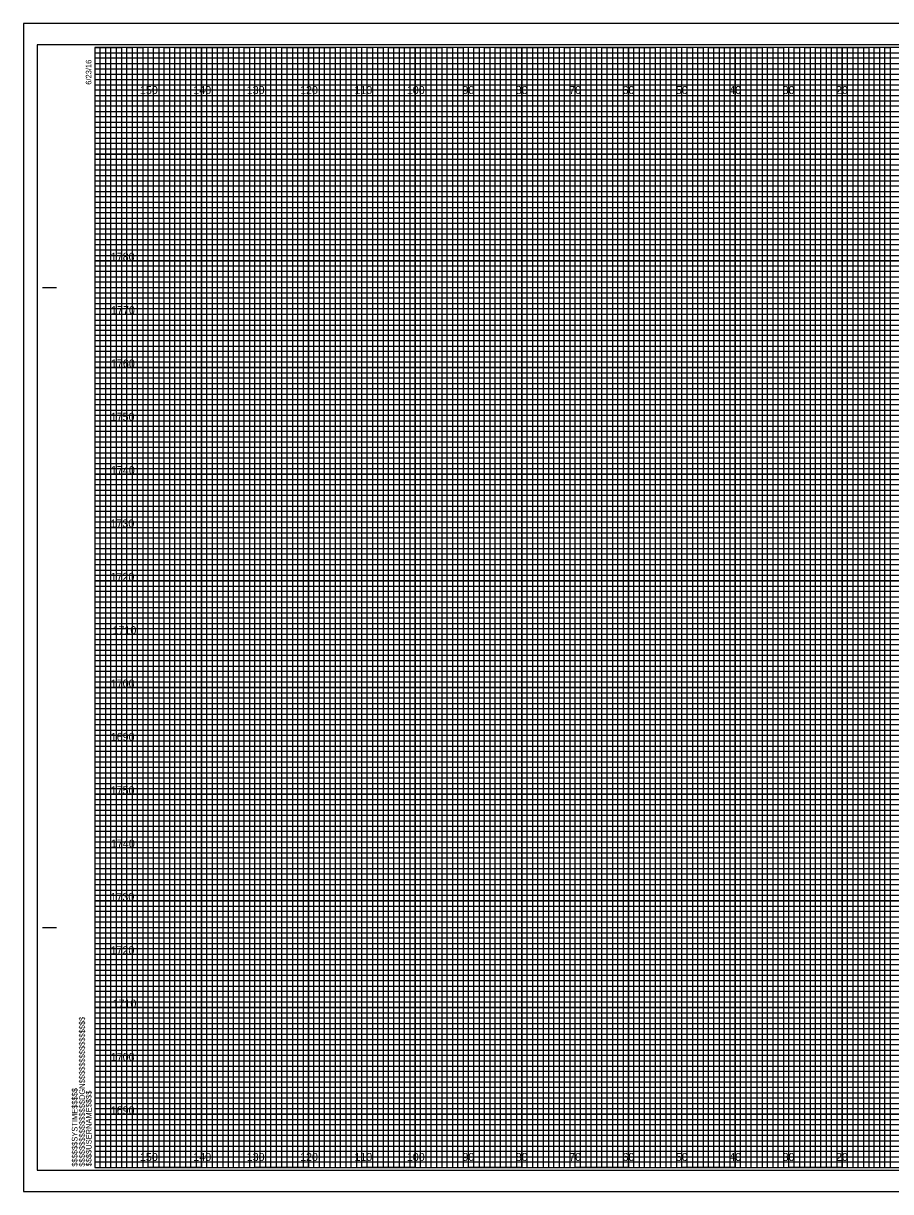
# Model space of a CAD drawing. Extents: x 185 to 522, y -7 to 872.
# Drawn here: x 184.8 to 347.3, y 433.5 to 652.5 of the extents above; entities that cross this region are included whole.
import ezdxf

# ---------------------------------------------------------------- set-up
doc = ezdxf.new("R2010")
doc.units = 0
for name, color, linetype in [('Raster_Level_0', 7, 'Continuous'), ('Scratch_Level_3', 7, 'Continuous'), ('Sheet Cross Section CELL', 7, 'Continuous'), ('Sheet Cross Section Grid Major CELL', 7, 'Continuous'), ('Sheet Cross Section Grid Middle CELL', 7, 'Continuous'), ('Sheet Cross Section Grid Minor 1 CELL', 7, 'Continuous'), ('Sheet Cross Section Grid Minor 2 CELL', 7, 'Continuous'), ('Sheet Cutting Line CELL', 7, 'Continuous'), ('Sheet DOT Grid CELL', 7, 'Continuous'), ('Sheet Plot Border Inside CELL', 7, 'Continuous'), ('Sheet Plot Border Outside CELL', 7, 'Continuous')]:
    doc.layers.add(name, color=color, linetype=linetype)

msp = doc.modelspace()

# ---------------------------------------------------------------- linework, layer by layer
at = {"layer": 'Sheet Cross Section CELL'}
for p, q in [((188.44, 602.95), (190.94, 602.95)), ((188.54, 602.95), (191.04, 602.95)), ((188.44, 482.95), (190.94, 482.95)), ((188.54, 482.95), (191.04, 482.95)), ((198.24, 437.95), (198.24, 437.95)), ((198.24, 437.95), (198.24, 437.95)), ((198.24, 437.95), (198.24, 437.95)), ((198.24, 437.95), (198.24, 437.95)), ((198.24, 437.95), (198.24, 437.95)), ((198.24, 437.95), (198.24, 437.95)), ((198.24, 437.95), (198.24, 437.95))]:
    msp.add_line(p, q, dxfattribs=at)
msp.add_lwpolyline([(518.24, 647.95), (198.24, 647.95), (198.24, 437.95), (518.24, 437.95)], close=True, dxfattribs=at)
at = {"layer": 'Sheet Cross Section Grid Major CELL'}
for p, q in [((208.24, 647.95), (198.24, 647.95)), ((208.24, 437.95), (208.24, 647.95)), ((228.24, 647.95), (218.24, 647.95)), ((218.24, 647.95), (218.24, 437.95)), ((228.24, 437.95), (228.24, 647.95)), ((248.24, 647.95), (238.24, 647.95)), ((238.24, 647.95), (238.24, 437.95)), ((248.24, 437.95), (248.24, 647.95)), ((268.24, 647.95), (258.24, 647.95)), ((258.24, 647.95), (258.24, 437.95)), ((268.24, 437.95), (268.24, 647.95)), ((288.24, 647.95), (278.24, 647.95)), ((278.24, 647.95), (278.24, 437.95)), ((288.24, 437.95), (288.24, 647.95)), ((308.24, 647.95), (298.24, 647.95)), ((298.24, 647.95), (298.24, 437.95)), ((308.24, 437.95), (308.24, 647.95)), ((328.24, 647.95), (318.24, 647.95)), ((318.24, 647.95), (318.24, 437.95)), ((328.24, 437.95), (328.24, 647.95)), ((348.24, 647.95), (338.24, 647.95)), ((338.24, 647.95), (338.24, 437.95)), ((218.24, 437.95), (208.24, 437.95)), ((238.24, 437.95), (228.24, 437.95)), ((258.24, 437.95), (248.24, 437.95)), ((278.24, 437.95), (268.24, 437.95)), ((298.24, 437.95), (288.24, 437.95)), ((318.24, 437.95), (308.24, 437.95)), ((338.24, 437.95), (328.24, 437.95))]:
    msp.add_line(p, q, dxfattribs=at)
for points in [[(198.24, 637.95), (518.24, 637.95), (518.24, 627.95), (198.24, 627.95)], [(198.24, 617.95), (518.24, 617.95), (518.24, 607.95), (198.24, 607.95)], [(198.24, 597.95), (518.24, 597.95), (518.24, 587.95), (198.24, 587.95)], [(198.24, 577.95), (518.24, 577.95), (518.24, 567.95), (198.24, 567.95)], [(198.24, 557.95), (518.24, 557.95), (518.24, 547.95), (198.24, 547.95)], [(198.24, 537.95), (518.24, 537.95), (518.24, 527.95), (198.24, 527.95)], [(198.24, 517.95), (518.24, 517.95), (518.24, 507.95), (198.24, 507.95)], [(198.24, 497.95), (518.24, 497.95), (518.24, 487.95), (198.24, 487.95)], [(198.24, 477.95), (518.24, 477.95), (518.24, 467.95), (198.24, 467.95)], [(198.24, 457.95), (518.24, 457.95), (518.24, 447.95), (198.24, 447.95)]]:
    msp.add_lwpolyline(points, dxfattribs=at)
at = {"layer": 'Sheet Cross Section Grid Middle CELL'}
for points in [[(198.24, 647.95), (203.24, 647.95), (203.24, 437.95), (213.24, 437.95), (213.24, 647.95), (223.24, 647.95), (223.24, 437.95), (233.24, 437.95), (233.24, 647.95), (243.24, 647.95), (243.24, 437.95), (253.24, 437.95), (253.24, 647.95), (263.24, 647.95), (263.24, 437.95), (273.24, 437.95), (273.24, 647.95), (283.24, 647.95), (283.24, 437.95), (293.24, 437.95), (293.24, 647.95), (303.24, 647.95), (303.24, 437.95), (313.24, 437.95), (313.24, 647.95), (323.24, 647.95), (323.24, 437.95), (333.24, 437.95), (333.24, 647.95), (343.24, 647.95), (343.24, 437.95), (353.24, 437.95)], [(198.24, 642.95), (473.24, 642.95)], [(198.24, 622.95), (518.24, 622.95), (518.24, 632.95), (198.24, 632.95)], [(198.24, 602.95), (518.24, 602.95), (518.24, 612.95), (198.24, 612.95)], [(198.24, 582.95), (518.24, 582.95), (518.24, 592.95), (198.24, 592.95)], [(198.24, 562.95), (518.24, 562.95), (518.24, 572.95), (198.24, 572.95)], [(198.24, 542.95), (518.24, 542.95), (518.24, 552.95), (198.24, 552.95)], [(198.24, 522.95), (518.24, 522.95), (518.24, 532.95), (198.24, 532.95)], [(198.24, 502.95), (518.24, 502.95), (518.24, 512.95), (198.24, 512.95)], [(198.24, 482.95), (518.24, 482.95), (518.24, 492.95), (198.24, 492.95)], [(198.24, 462.95), (518.24, 462.95), (518.24, 472.95), (198.24, 472.95)], [(198.24, 442.95), (518.24, 442.95), (518.24, 452.95), (198.24, 452.95)]]:
    msp.add_lwpolyline(points, dxfattribs=at)
at = {"layer": 'Sheet Cross Section Grid Minor 1 CELL'}
for p, q in [((198.24, 646.95), (458.24, 646.95)), ((458.24, 645.93), (198.24, 645.93)), ((198.24, 645.93), (198.24, 644.95)), ((198.24, 644.95), (458.24, 644.95)), ((458.24, 643.84), (198.24, 643.84)), ((198.24, 643.84), (198.24, 641.95)), ((198.24, 641.95), (518.24, 641.95))]:
    msp.add_line(p, q, dxfattribs=at)
for points in [[(198.24, 640.95), (468.24, 640.95), (518.24, 640.95), (518.24, 639.95), (198.24, 639.95)], [(198.24, 638.95), (518.24, 638.95), (518.24, 636.95), (198.24, 636.95)], [(198.24, 635.95), (518.24, 635.95), (518.24, 634.95), (198.24, 634.93)], [(198.24, 633.95), (518.24, 633.95), (518.24, 631.95), (198.24, 631.95)], [(198.24, 630.95), (518.24, 630.95), (518.24, 629.95), (198.24, 629.95)], [(198.24, 628.95), (518.24, 628.95), (518.24, 626.95), (198.24, 626.95)], [(198.24, 625.95), (518.24, 625.95), (518.24, 624.95), (198.24, 624.95)], [(198.24, 623.95), (518.24, 623.95), (518.24, 621.95), (198.24, 621.95)], [(198.24, 620.95), (518.24, 620.95), (518.24, 619.95), (198.24, 619.95)], [(198.24, 618.95), (518.24, 618.95), (518.24, 616.95), (198.24, 616.95)], [(198.24, 615.95), (518.24, 615.95), (518.24, 614.95), (198.24, 614.95)], [(198.24, 613.95), (518.24, 613.95), (518.24, 611.9), (518.24, 610.95), (518.24, 609.95), (198.24, 609.95)], [(198.24, 611.95), (518.24, 611.95), (518.24, 610.95), (198.24, 610.95)], [(198.24, 608.95), (518.24, 608.95), (518.24, 606.95), (198.24, 606.98)], [(198.24, 606.98), (518.24, 606.95), (518.24, 605.95), (198.24, 605.95)], [(198.24, 604.95), (518.24, 604.95), (518.24, 603.95), (198.24, 603.95)], [(198.24, 601.95), (518.24, 601.95), (518.24, 600.95), (198.24, 600.95)], [(198.24, 599.95), (518.24, 599.95), (518.24, 598.95), (198.24, 598.95)], [(198.17, 596.84), (518.24, 596.84), (518.24, 595.83), (198.17, 595.83)], [(198.24, 594.95), (518.24, 594.95), (518.24, 593.95), (198.24, 593.95)], [(198.24, 591.95), (518.24, 591.95), (518.24, 590.95), (198.24, 590.95)], [(198.24, 589.95), (518.24, 589.95), (518.24, 588.95), (198.24, 588.95)], [(198.24, 586.95), (518.24, 586.95), (518.24, 585.95), (198.24, 585.95)], [(198.24, 584.95), (518.24, 584.95), (518.24, 583.95), (198.24, 583.95)], [(198.24, 581.95), (518.24, 581.95), (518.24, 580.95), (198.24, 580.95)], [(198.24, 579.95), (518.24, 579.95), (518.24, 578.95), (198.24, 578.95)], [(198.24, 576.95), (518.24, 576.95), (518.23, 575.93), (198.24, 575.95)], [(198.24, 574.95), (518.24, 574.95), (518.24, 573.95), (198.24, 573.95)], [(198.24, 571.95), (518.24, 571.95), (518.24, 570.95), (198.24, 570.95)], [(198.24, 569.95), (518.24, 569.95), (518.24, 568.95), (198.24, 568.95)], [(198.24, 566.95), (518.24, 566.95), (518.24, 565.95), (198.24, 565.95)], [(198.24, 564.95), (518.24, 564.95), (518.24, 563.95), (198.24, 563.95)], [(198.24, 561.95), (518.24, 561.95), (518.24, 560.95), (198.24, 560.95)], [(198.24, 559.95), (518.24, 559.95), (518.24, 558.95), (198.24, 558.95)], [(198.24, 556.95), (518.24, 556.95), (518.24, 555.95), (198.24, 555.95)], [(198.24, 554.94), (518.31, 554.86), (518.24, 553.95), (198.24, 553.95)], [(198.24, 551.95), (518.24, 551.95), (518.24, 550.95), (198.24, 550.95)], [(198.24, 549.95), (518.24, 549.95), (518.24, 548.95), (198.24, 548.95)], [(198.24, 546.95), (518.24, 546.95), (518.24, 545.95), (198.24, 545.95)], [(198.24, 544.95), (518.24, 544.95), (518.24, 543.95), (198.24, 543.95)], [(198.24, 541.95), (518.24, 541.95), (518.24, 540.95), (198.24, 540.95)], [(198.24, 539.95), (518.24, 539.95), (518.24, 538.95), (198.24, 538.95)], [(198.24, 536.95), (518.24, 536.95), (518.24, 535.95), (198.24, 535.95)], [(198.24, 534.95), (518.24, 534.95), (518.24, 533.95), (198.24, 533.95)], [(198.24, 531.95), (518.24, 531.95), (518.24, 530.95), (198.24, 530.95)], [(198.24, 529.95), (518.24, 529.95), (518.24, 528.95), (198.24, 528.95)], [(198.24, 526.95), (518.24, 526.95), (518.24, 525.95), (198.24, 525.95)], [(198.24, 524.95), (518.24, 524.95), (518.24, 523.95), (198.24, 523.95)], [(198.24, 521.95), (518.24, 521.95), (518.24, 520.95), (198.24, 520.95)], [(198.24, 519.95), (518.24, 519.95), (518.24, 518.95), (198.24, 518.95)], [(198.24, 516.95), (518.24, 516.95), (518.23, 515.93), (198.24, 515.95)], [(198.24, 514.95), (518.24, 514.95), (518.24, 513.95), (198.24, 513.95)], [(198.24, 511.95), (518.24, 511.95), (518.24, 510.95), (198.24, 510.95)], [(198.24, 509.95), (518.24, 509.95), (518.24, 508.95), (198.24, 508.95)], [(198.24, 506.95), (518.24, 506.95), (518.24, 505.95), (198.24, 505.95)], [(198.24, 504.95), (518.24, 504.95), (518.24, 503.95), (198.24, 503.95)], [(198.24, 501.95), (518.24, 501.95), (518.24, 500.95), (198.24, 500.95)], [(198.24, 499.95), (518.24, 499.95), (518.24, 498.95), (198.24, 498.95)], [(198.24, 496.95), (518.24, 496.95), (518.24, 495.95), (198.24, 495.95)], [(198.24, 494.94), (518.31, 494.86), (518.24, 493.95), (198.24, 493.95)], [(198.24, 491.95), (518.24, 491.95), (518.24, 490.95), (198.24, 490.95)], [(198.24, 489.95), (518.24, 489.95), (518.24, 488.95), (198.24, 488.95)], [(198.24, 486.95), (518.24, 486.95), (518.24, 485.95), (198.24, 485.95)], [(198.24, 484.95), (518.24, 484.95), (518.24, 483.95), (198.24, 483.95)], [(198.24, 481.95), (518.24, 481.95), (518.24, 480.95), (198.24, 480.95)], [(198.24, 479.95), (518.24, 479.95), (518.24, 478.95), (198.24, 478.95)], [(198.24, 476.95), (518.24, 476.95), (518.24, 475.95), (198.24, 475.95)], [(198.24, 474.95), (518.24, 474.95), (518.24, 473.95), (198.24, 473.95)], [(198.24, 471.95), (518.24, 471.95), (518.24, 470.95), (198.24, 470.95)], [(198.24, 469.95), (518.24, 469.95), (518.24, 468.95), (198.24, 468.95)], [(198.24, 466.95), (518.24, 466.95), (518.24, 465.95), (198.24, 465.95)], [(198.24, 464.95), (518.24, 464.95), (518.24, 463.95), (198.24, 463.95)], [(198.24, 461.95), (518.24, 461.95), (518.24, 460.95), (198.24, 460.95)], [(198.24, 459.95), (518.24, 459.95), (518.24, 458.95), (198.24, 458.95)], [(198.24, 456.95), (518.24, 456.95), (518.24, 455.95), (198.24, 455.95)], [(198.24, 454.95), (518.24, 454.95), (518.24, 453.95), (198.24, 453.95)], [(198.24, 451.95), (518.24, 451.95), (518.24, 450.95), (198.24, 450.95)], [(198.24, 449.95), (518.24, 449.95), (518.24, 448.95), (198.24, 448.95)], [(198.24, 446.95), (518.24, 446.95), (518.24, 445.95), (198.24, 445.95)], [(198.24, 444.95), (518.24, 444.95), (518.24, 443.95), (198.24, 443.95)], [(198.24, 441.95), (518.24, 441.95), (518.24, 440.95), (198.24, 440.95)], [(198.24, 439.95), (518.24, 439.95), (518.24, 438.95), (198.24, 438.95)]]:
    msp.add_lwpolyline(points, dxfattribs=at)
at = {"layer": 'Sheet Cross Section Grid Minor 2 CELL'}
for points in [[(198.24, 437.95), (199.24, 437.95), (199.24, 647.95), (200.24, 647.95), (200.24, 437.95)], [(200.24, 437.95), (201.24, 437.95), (201.24, 647.95), (202.24, 647.95), (202.24, 437.95)], [(203.24, 437.95), (204.24, 437.95), (204.24, 647.95), (205.24, 647.95), (205.24, 437.95)], [(205.24, 437.95), (206.24, 437.95), (206.24, 647.95), (207.24, 647.95), (207.24, 437.95)], [(208.24, 437.95), (209.24, 437.95), (209.24, 647.95), (210.24, 647.95), (210.24, 437.95)], [(210.24, 437.95), (211.24, 437.95), (211.24, 647.95), (212.24, 647.95), (212.24, 437.95)], [(213.24, 437.95), (214.24, 437.95), (214.24, 647.95), (215.24, 647.95), (215.24, 437.95)], [(215.24, 437.95), (216.24, 437.95), (216.24, 647.95), (217.24, 647.95), (217.24, 437.95)], [(218.24, 437.95), (219.24, 437.95), (219.24, 647.95), (220.24, 647.95), (220.24, 437.95)], [(220.24, 437.95), (221.24, 437.95), (221.24, 647.95), (222.24, 647.95), (222.24, 437.95)], [(223.24, 437.95), (224.24, 437.95), (224.24, 647.95), (225.24, 647.95), (225.24, 437.95)], [(225.24, 437.95), (226.24, 437.95), (226.24, 647.95), (227.24, 647.95), (227.24, 437.95)], [(228.24, 437.95), (229.24, 437.95), (229.24, 647.95), (230.24, 647.95), (230.24, 437.95)], [(230.24, 437.95), (231.24, 437.95), (231.24, 647.95), (232.24, 647.95), (232.24, 437.95)], [(233.24, 437.95), (234.24, 437.95), (234.24, 647.95), (235.24, 647.95), (235.24, 437.95)], [(235.24, 437.95), (236.24, 437.95), (236.24, 647.95), (237.24, 647.95), (237.24, 437.95)], [(238.24, 437.95), (239.24, 437.95), (239.24, 647.95), (240.24, 647.95), (240.24, 437.95)], [(240.24, 437.95), (241.24, 437.95), (241.24, 647.95), (242.24, 647.95), (242.24, 437.95)], [(243.24, 437.95), (244.24, 437.95), (244.24, 647.95), (245.24, 647.95), (245.24, 437.95)], [(245.24, 437.95), (246.24, 437.95), (246.24, 647.95), (247.24, 647.95), (247.24, 437.95)], [(248.24, 437.95), (249.24, 437.95), (249.24, 647.95), (250.24, 647.95), (250.24, 437.95)], [(250.24, 437.95), (251.24, 437.95), (251.24, 647.95), (252.24, 647.95), (252.24, 437.95)], [(253.24, 437.95), (254.24, 437.95), (254.24, 647.95), (255.24, 647.95), (255.24, 437.95)], [(255.24, 437.95), (256.24, 437.95), (256.24, 647.95), (257.24, 647.95), (257.24, 437.95)], [(258.24, 437.95), (259.24, 437.95), (259.24, 647.95), (260.24, 647.95), (260.24, 437.95)], [(260.24, 437.95), (261.24, 437.95), (261.24, 647.95), (262.24, 647.95), (262.24, 437.95)], [(263.24, 437.95), (264.24, 437.95), (264.24, 647.95), (265.24, 647.95), (265.24, 437.95)], [(265.24, 437.95), (266.24, 437.95), (266.24, 647.95), (267.24, 647.95), (267.24, 437.95)], [(268.24, 437.95), (269.24, 437.95), (269.24, 647.95), (270.24, 647.95), (270.24, 437.95)], [(270.24, 437.95), (271.24, 437.95), (271.24, 647.95), (272.24, 647.95), (272.24, 437.95)], [(273.24, 437.95), (274.24, 437.95), (274.24, 647.95), (275.24, 647.95), (275.24, 437.95)], [(275.24, 437.95), (276.24, 437.95), (276.24, 647.95), (277.24, 647.95), (277.24, 437.95)], [(278.24, 437.95), (279.24, 437.95), (279.24, 647.95), (280.24, 647.95), (280.24, 437.95)], [(280.24, 437.95), (281.24, 437.95), (281.24, 647.95), (282.24, 647.95), (282.24, 437.95)], [(283.24, 437.95), (284.24, 437.95), (284.24, 647.95), (285.24, 647.95), (285.24, 437.95)], [(285.24, 437.95), (286.24, 437.95), (286.24, 647.95), (287.24, 647.95), (287.24, 437.95)], [(288.24, 437.95), (289.24, 437.95), (289.24, 647.95), (290.24, 647.95), (290.24, 437.95)], [(290.24, 437.95), (291.24, 437.95), (291.24, 647.95), (292.24, 647.95), (292.24, 437.95)], [(293.24, 437.95), (294.24, 437.95), (294.24, 647.95), (295.24, 647.95), (295.24, 437.95)], [(295.24, 437.95), (296.24, 437.95), (296.24, 647.95), (297.24, 647.95), (297.24, 437.95)], [(298.24, 437.95), (299.24, 437.95), (299.24, 647.95), (300.24, 647.95), (300.24, 437.95)], [(300.24, 437.95), (301.24, 437.95), (301.24, 647.95), (302.24, 647.95), (302.24, 437.95)], [(303.24, 437.95), (304.24, 437.95), (304.24, 647.95), (305.24, 647.95), (305.24, 437.95)], [(305.24, 437.95), (306.24, 437.95), (306.24, 647.95), (307.24, 647.95), (307.24, 437.95)], [(308.24, 437.95), (309.24, 437.95), (309.24, 647.95), (310.24, 647.95), (310.24, 437.95)], [(310.24, 437.95), (311.24, 437.95), (311.24, 647.95), (312.24, 647.95), (312.24, 437.95)], [(313.24, 437.95), (314.24, 437.95), (314.24, 647.95), (315.24, 647.95), (315.24, 437.95)], [(315.24, 437.95), (316.24, 437.95), (316.24, 647.95), (317.24, 647.95), (317.24, 437.95)], [(318.24, 437.95), (319.24, 437.95), (319.24, 647.95), (320.24, 647.95), (320.24, 437.95)], [(320.24, 437.95), (321.24, 437.95), (321.24, 647.95), (322.24, 647.95), (322.24, 437.95)], [(323.24, 437.95), (324.24, 437.95), (324.24, 647.95), (325.24, 647.95), (325.24, 437.95)], [(325.24, 437.95), (326.24, 437.95), (326.24, 647.95), (327.24, 647.95), (327.24, 437.95)], [(328.24, 437.95), (329.24, 437.95), (329.24, 647.95), (330.24, 647.95), (330.24, 437.95)], [(330.24, 437.95), (331.24, 437.95), (331.24, 647.95), (332.24, 647.95), (332.24, 437.95)], [(333.24, 437.95), (334.24, 437.95), (334.24, 647.95), (335.24, 647.95), (335.24, 437.95)], [(335.24, 437.95), (336.24, 437.95), (336.24, 647.95), (337.24, 647.95), (337.24, 437.95)], [(338.24, 437.95), (339.24, 437.95), (339.24, 647.95), (340.24, 647.95), (340.24, 437.95)], [(340.24, 437.95), (341.24, 437.95), (341.24, 647.95), (342.24, 647.95), (342.24, 437.95)], [(343.24, 437.95), (344.24, 437.95), (344.24, 647.95), (345.24, 647.95), (345.24, 437.95)], [(345.24, 437.95), (346.24, 437.95), (346.24, 647.95), (347.24, 647.95), (347.24, 437.95)]]:
    msp.add_lwpolyline(points, dxfattribs=at)
at = {"layer": 'Sheet Cutting Line CELL'}
for p, q in [((521.54, 652.45), (184.84, 652.45)), ((184.84, 652.45), (184.84, 433.45)), ((184.84, 433.45), (521.54, 433.45))]:
    msp.add_line(p, q, dxfattribs=at)
at = {"layer": 'Sheet DOT Grid CELL'}
for p, q in [((208.24, 437.95), (208.24, 647.95)), ((218.24, 437.95), (218.24, 647.95)), ((228.24, 437.95), (228.24, 647.95)), ((238.24, 437.95), (238.24, 647.95)), ((248.24, 437.95), (248.24, 647.95)), ((258.24, 437.95), (258.24, 647.95)), ((268.24, 437.95), (268.24, 647.95)), ((278.24, 437.95), (278.24, 647.95)), ((288.24, 437.95), (288.24, 647.95)), ((298.24, 437.95), (298.24, 647.95)), ((308.24, 437.95), (308.24, 647.95)), ((318.24, 437.95), (318.24, 647.95)), ((328.24, 437.95), (328.24, 647.95)), ((338.24, 437.95), (338.24, 647.95)), ((198.24, 637.95), (518.24, 637.95)), ((198.24, 627.95), (518.24, 627.95)), ((198.24, 617.95), (518.24, 617.95)), ((198.24, 607.95), (518.24, 607.95)), ((198.24, 597.95), (518.24, 597.95)), ((198.24, 587.95), (518.24, 587.95)), ((198.24, 577.95), (518.24, 577.95)), ((198.24, 567.95), (518.24, 567.95)), ((198.24, 557.95), (518.24, 557.95)), ((198.24, 547.95), (518.24, 547.95)), ((198.24, 537.95), (518.24, 537.95)), ((198.24, 527.95), (518.24, 527.95)), ((198.24, 517.95), (518.24, 517.95)), ((198.24, 507.95), (518.24, 507.95)), ((198.24, 497.95), (518.24, 497.95)), ((198.24, 487.95), (518.24, 487.95)), ((198.24, 477.95), (518.24, 477.95)), ((198.24, 467.95), (518.24, 467.95)), ((198.24, 457.95), (518.24, 457.95)), ((198.24, 447.95), (518.24, 447.95))]:
    msp.add_line(p, q, dxfattribs=at)
at = {"layer": 'Sheet Plot Border Inside CELL'}
msp.add_lwpolyline([(187.44, 437.45), (520.64, 437.45), (520.64, 648.45), (187.44, 648.45)], close=True, dxfattribs=at)
at = {"layer": 'Sheet Plot Border Outside CELL'}
msp.add_lwpolyline([(184.84, 433.45), (521.54, 433.45), (521.54, 652.45), (184.84, 652.45)], close=True, dxfattribs=at)

# ---------------------------------------------------------------- texts
at = {"layer": 'Raster_Level_0'}
for s, p in [('150', (206.69, 639.2)), ('140', (216.69, 639.2)), ('130', (226.69, 639.2)), ('120', (236.69, 639.2)), ('110', (246.87, 639.2)), ('100', (256.69, 639.2)), ('90', (267.1, 639.2)), ('80', (277.1, 639.2)), ('70', (287.1, 639.2)), ('60', (297.1, 639.2)), ('50', (307.1, 639.2)), ('40', (317.1, 639.2)), ('30', (327.1, 639.2)), ('20', (337.1, 639.2)), ('150', (206.69, 439.2)), ('140', (216.69, 439.2)), ('130', (226.69, 439.2)), ('120', (236.69, 439.2)), ('110', (246.87, 439.2)), ('100', (256.69, 439.2)), ('90', (267.1, 439.2)), ('80', (277.1, 439.2)), ('70', (287.1, 439.2)), ('60', (297.1, 439.2)), ('50', (307.1, 439.2)), ('40', (317.1, 439.2)), ('30', (327.1, 439.2)), ('20', (337.1, 439.2))]:
    msp.add_text(s, height=1.5, dxfattribs=at).set_placement(p)
at = {"layer": 'Scratch_Level_3'}
for s, p in [('1780', (201.22, 607.95)), ('1770', (201.28, 597.95)), ('1760', (201.25, 587.95)), ('1750', (201.2, 577.95)), ('1740', (201.25, 567.95)), ('1730', (201.17, 557.95)), ('1720', (201.18, 547.95)), ('1710', (201.55, 537.95)), ('1700', (201.22, 527.95)), ('1690', (201.21, 517.95)), ('1750', (201.2, 507.95)), ('1740', (201.25, 497.95)), ('1730', (201.17, 487.95)), ('1720', (201.18, 477.95)), ('1710', (201.55, 467.95)), ('1700', (201.22, 457.95)), ('1690', (201.21, 447.95))]:
    msp.add_text(s, height=1.5, dxfattribs=at).set_placement(p)
at = {"layer": 'Sheet Cross Section CELL'}
for s, p in [('6/23/16', (197.59, 640.95)), ('$$$$$$$$$$$$$$$$DGN$$$$$$$$$$$$$$$$', (196.36, 438.13)), ('$$$$$$SYSTIME$$$$$', (194.98, 438.13)), ('$$$$USERNAME$$$$', (197.62, 438.18))]:
    msp.add_text(s, height=1.05, rotation=90, dxfattribs=at).set_placement(p)

doc.saveas('drawing.dxf')
